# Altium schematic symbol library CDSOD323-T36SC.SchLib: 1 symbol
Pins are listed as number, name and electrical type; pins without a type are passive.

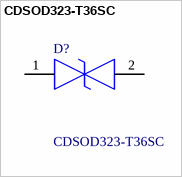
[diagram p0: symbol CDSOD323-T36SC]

## CDSOD323-T36SC
designator D?
BOURNS - CDSOD323-T36SC - DIODE, TVS, BI, 500W, 36V, SOD-323; Geometry.Height: 1.14mm
footprint SOD2513X114N
pins: 1, 2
